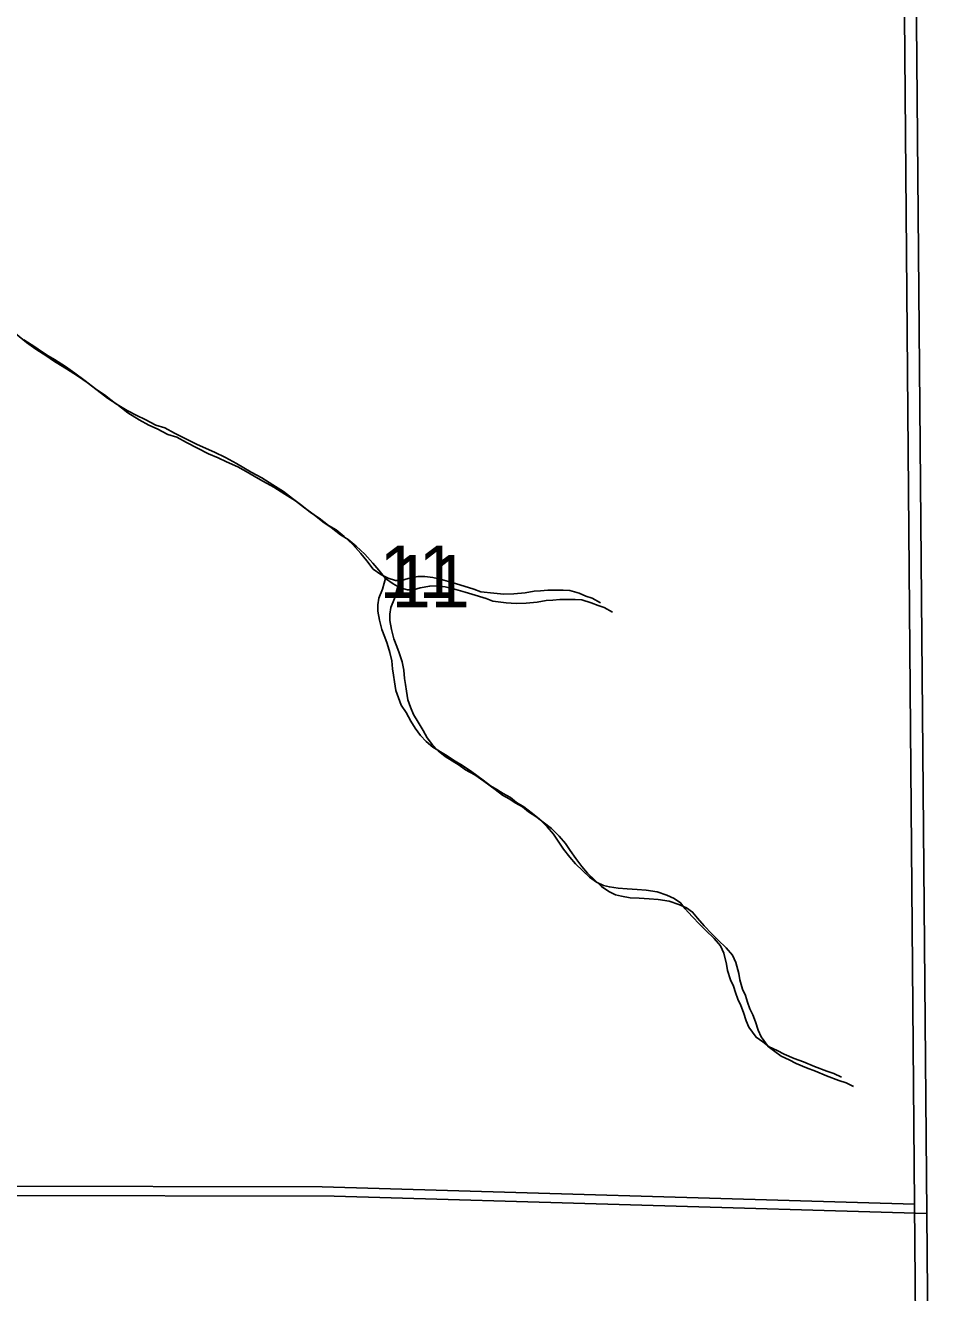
# Model space of a CAD drawing. Extents: x -21.1 to 50.3, y -4.9 to 22.1.
# Drawn here: x 48.475 to 49.204, y 17.623 to 18.636 of the extents above; entities that cross this region are included whole.
import ezdxf

# ---------------------------------------------------------------- set-up
doc = ezdxf.new("R2010")
doc.units = 0
for name, color, linetype in [('GM_X_Minor_River', 7, 'Continuous'), ('GM_X_Section', 7, 'Continuous'), ('GM_X_Section_Text', 7, 'Continuous')]:
    doc.layers.add(name, color=color, linetype=linetype)

msp = doc.modelspace()

# ---------------------------------------------------------------- linework, layer by layer
at = {"layer": 'GM_X_Minor_River'}
for points in [[(48.4669, 18.3899), (48.4757, 18.3828), (48.4833, 18.3775), (48.4921, 18.3718), (48.4974, 18.3681), (48.5028, 18.3647), (48.5077, 18.3617), (48.5165, 18.356), (48.5242, 18.3507), (48.5322, 18.3447), (48.5406, 18.3383), (48.5479, 18.3334), (48.5567, 18.3266), (48.5658, 18.3209), (48.5735, 18.3168), (48.5803, 18.3138), (48.5887, 18.3093), (48.596, 18.3071), (48.6036, 18.3029), (48.6212, 18.2939), (48.6288, 18.2905), (48.6357, 18.2875), (48.6445, 18.2834), (48.6532, 18.2785), (48.659, 18.2751), (48.6651, 18.2717), (48.6735, 18.2672), (48.6823, 18.2616), (48.6907, 18.2563), (48.6979, 18.2506), (48.7056, 18.245), (48.7125, 18.2393), (48.7193, 18.2348), (48.7266, 18.2291), (48.7327, 18.2254), (48.7392, 18.2201), (48.7461, 18.2137), (48.7526, 18.2065)], [(48.4737, 18.385), (48.4824, 18.3793), (48.4878, 18.3756), (48.4931, 18.3722), (48.4981, 18.3692), (48.5069, 18.3635), (48.5145, 18.3582), (48.5226, 18.3522), (48.531, 18.3458), (48.5382, 18.3409), (48.547, 18.3341), (48.5562, 18.3284), (48.5638, 18.3243), (48.5707, 18.3213), (48.5791, 18.3168), (48.5863, 18.3146), (48.594, 18.3104), (48.6115, 18.3014), (48.6192, 18.298), (48.626, 18.295), (48.6348, 18.2909), (48.6436, 18.286), (48.6493, 18.2826), (48.6554, 18.2792), (48.6638, 18.2747), (48.6726, 18.2691), (48.681, 18.2638), (48.6883, 18.2581), (48.6959, 18.2525), (48.7028, 18.2468), (48.7097, 18.2423), (48.717, 18.2366), (48.7231, 18.2329), (48.7296, 18.2276), (48.7365, 18.2212), (48.743, 18.214)], [(48.743, 18.214), (48.7476, 18.2083), (48.7529, 18.2015), (48.759, 18.1974), (48.7648, 18.1944), (48.7705, 18.1925), (48.7754, 18.1925), (48.7808, 18.1941), (48.7884, 18.1956), (48.7941, 18.1957), (48.8005, 18.1949), (48.8074, 18.1934), (48.8166, 18.1908), (48.8219, 18.189), (48.8333, 18.1856), (48.8387, 18.1834), (48.8493, 18.1823), (48.8573, 18.1816), (48.8653, 18.182), (48.8741, 18.1828), (48.8813, 18.184), (48.8866, 18.1844), (48.8923, 18.1848), (48.9045, 18.1849), (48.9099, 18.1845), (48.9175, 18.1823), (48.9228, 18.18), (48.9278, 18.1785), (48.9343, 18.1748)], [(48.7526, 18.2065), (48.7572, 18.2008), (48.7626, 18.194), (48.7687, 18.1899), (48.7744, 18.1868), (48.7801, 18.185), (48.7851, 18.185), (48.7904, 18.1866), (48.798, 18.1881), (48.8037, 18.1882), (48.8102, 18.1874), (48.817, 18.1859), (48.8262, 18.1833), (48.8315, 18.1815), (48.843, 18.1781), (48.8483, 18.1759), (48.859, 18.1748), (48.867, 18.1741), (48.875, 18.1745), (48.8837, 18.1753), (48.8909, 18.1765), (48.8963, 18.1769), (48.902, 18.1773), (48.9142, 18.1774), (48.9195, 18.177), (48.9271, 18.1748), (48.9325, 18.1725), (48.9374, 18.171), (48.9439, 18.1673)], [(48.7629, 18.1953), (48.7603, 18.1856), (48.7572, 18.1784), (48.7565, 18.173), (48.7565, 18.1681), (48.7577, 18.1609), (48.7597, 18.1533), (48.762, 18.1472), (48.7639, 18.1423), (48.7662, 18.1351), (48.7678, 18.1283), (48.7682, 18.1218), (48.769, 18.1169), (48.7698, 18.1116), (48.771, 18.1047), (48.7729, 18.0987), (48.7752, 18.093), (48.7791, 18.0869), (48.7829, 18.0801), (48.7864, 18.0744), (48.7906, 18.0687), (48.7952, 18.0638), (48.8005, 18.0593), (48.812, 18.0525), (48.817, 18.0488), (48.8242, 18.0446), (48.8315, 18.0397), (48.8407, 18.0329), (48.8464, 18.0284), (48.8517, 18.0254), (48.8567, 18.0224), (48.8624, 18.019), (48.8674, 18.0152), (48.8731, 18.0115), (48.88, 18.0062), (48.8858, 18.0017), (48.8919, 17.9956), (48.8969, 17.9899), (48.9007, 17.9843), (48.9049, 17.9778), (48.9099, 17.9714), (48.9145, 17.9661), (48.9202, 17.9604), (48.9256, 17.9555), (48.9313, 17.9514), (48.9367, 17.9487), (48.9416, 17.9476), (48.9485, 17.9465), (48.9557, 17.9462), (48.9637, 17.9455), (48.9709, 17.9451), (48.9797, 17.9437), (48.9873, 17.941), (48.9934, 17.9384), (48.9984, 17.935), (49.0022, 17.9301), (49.0076, 17.9241), (49.0137, 17.9176), (49.0187, 17.9127), (49.0252, 17.9063), (49.0302, 17.9006), (49.0329, 17.8946), (49.0352, 17.8858), (49.036, 17.8809), (49.0383, 17.8733), (49.0407, 17.8684), (49.0422, 17.8631), (49.0441, 17.8578), (49.0465, 17.8529), (49.0488, 17.8472), (49.0507, 17.8407), (49.053, 17.8354), (49.0588, 17.8275), (49.0641, 17.8237), (49.0691, 17.8199), (49.0756, 17.8169), (49.0813, 17.8139), (49.0893, 17.8105), (49.0966, 17.8079), (49.1053, 17.8042), (49.1153, 17.8004), (49.121, 17.7986), (49.1271, 17.7956)], [(48.7726, 18.1878), (48.7699, 18.1781), (48.7669, 18.1709), (48.7662, 18.1655), (48.7662, 18.1606), (48.7674, 18.1534), (48.7693, 18.1458), (48.7716, 18.1397), (48.7736, 18.1348), (48.7759, 18.1276), (48.7774, 18.1208), (48.7779, 18.1143), (48.7787, 18.1094), (48.7794, 18.1041), (48.7806, 18.0972), (48.7826, 18.0912), (48.7849, 18.0855), (48.7887, 18.0794), (48.7926, 18.0726), (48.796, 18.0669), (48.8002, 18.0612), (48.8048, 18.0563), (48.8102, 18.0518), (48.8216, 18.045), (48.8266, 18.0413), (48.8339, 18.0371), (48.8411, 18.0322), (48.8503, 18.0254), (48.856, 18.0209), (48.8614, 18.0179), (48.8663, 18.0149), (48.8721, 18.0115), (48.877, 18.0077), (48.8828, 18.004), (48.8897, 17.9987), (48.8954, 17.9942), (48.9015, 17.9881), (48.9065, 17.9824), (48.9103, 17.9768), (48.9146, 17.9703), (48.9195, 17.9639), (48.9241, 17.9586), (48.9299, 17.9529), (48.9352, 17.948), (48.941, 17.9439), (48.9463, 17.9412), (48.9513, 17.9401), (48.9581, 17.939), (48.9654, 17.9387), (48.9734, 17.938), (48.9806, 17.9376), (48.9893, 17.9362), (48.997, 17.9335), (49.0031, 17.9309), (49.008, 17.9275), (49.0119, 17.9226), (49.0172, 17.9166), (49.0234, 17.9101), (49.0283, 17.9052), (49.0349, 17.8988), (49.0398, 17.8931), (49.0425, 17.8871), (49.0449, 17.8783), (49.0457, 17.8734), (49.048, 17.8658), (49.0503, 17.8609), (49.0518, 17.8556), (49.0538, 17.8503), (49.0561, 17.8454), (49.0584, 17.8397), (49.0603, 17.8332), (49.0627, 17.8279), (49.0684, 17.82), (49.0738, 17.8162), (49.0787, 17.8124), (49.0852, 17.8094), (49.0909, 17.8064), (49.099, 17.803), (49.1062, 17.8004), (49.115, 17.7967), (49.1249, 17.7929), (49.1306, 17.7911), (49.1367, 17.7881)]]:
    msp.add_lwpolyline(points, dxfattribs=at)
at = {"layer": 'GM_X_Section'}
for points in [[(48.1626, 18.7259), (49.1767, 18.7082), (49.1854, 17.694), (48.7119, 17.7079), (48.171, 17.7091)], [(48.1722, 18.7184), (49.1863, 18.7007), (49.1951, 17.6865), (48.7215, 17.7004), (48.1806, 17.7016)], [(48.171, 17.7091), (48.7119, 17.7079), (49.1854, 17.694), (49.1942, 16.6763), (48.6942, 16.687), (48.1855, 16.6839)], [(48.1806, 17.7016), (48.7215, 17.7004), (49.1951, 17.6865), (49.2038, 16.6688), (48.7038, 16.6795), (48.1952, 16.6764)]]:
    msp.add_lwpolyline(points, close=True, dxfattribs=at)

# ---------------------------------------------------------------- texts
at = {"layer": 'GM_X_Section_Text'}
for p in [(48.758, 18.1786), (48.7676, 18.1711)]:
    msp.add_text('11', height=0.04186, rotation=0, dxfattribs=at).set_placement(p)

doc.saveas('drawing.dxf')
